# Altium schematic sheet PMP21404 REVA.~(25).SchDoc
size 431 x 279 mm; Date: Not shown in title block; ApprovedBy: Not shown in title block; CheckedBy: Not shown in title block; Author: Not shown in title block; CompanyName: Not shown in title block; Engineer: Not shown in title block; Organization: Not shown in title block; Address1: Not shown in title block; Address2: Not shown in title block; Address3: Not shown in title block; Address4: Not shown in title block; DocumentNumber: 1; Revision: Use project parameter SCH_Rev; SheetNumber: 1; SheetTotal: 1; PageSetup: Record=PageOptions¦CenterHorizontal=True¦CenterVertical=True¦PrintScale=1.00¦XCorrection=1.00¦YCorrection=1.00¦PrintKind=0¦BorderSize=5000000¦LeftOffset=0¦BottomOffset=0¦Orientation=2¦PaperLength=1000¦PaperWidth=1000¦Scale=100¦PaperSource=15¦PrintQuality=600¦MediaType=1¦DitherType=10¦PaperKind=Letter¦PrintScaleMode=1
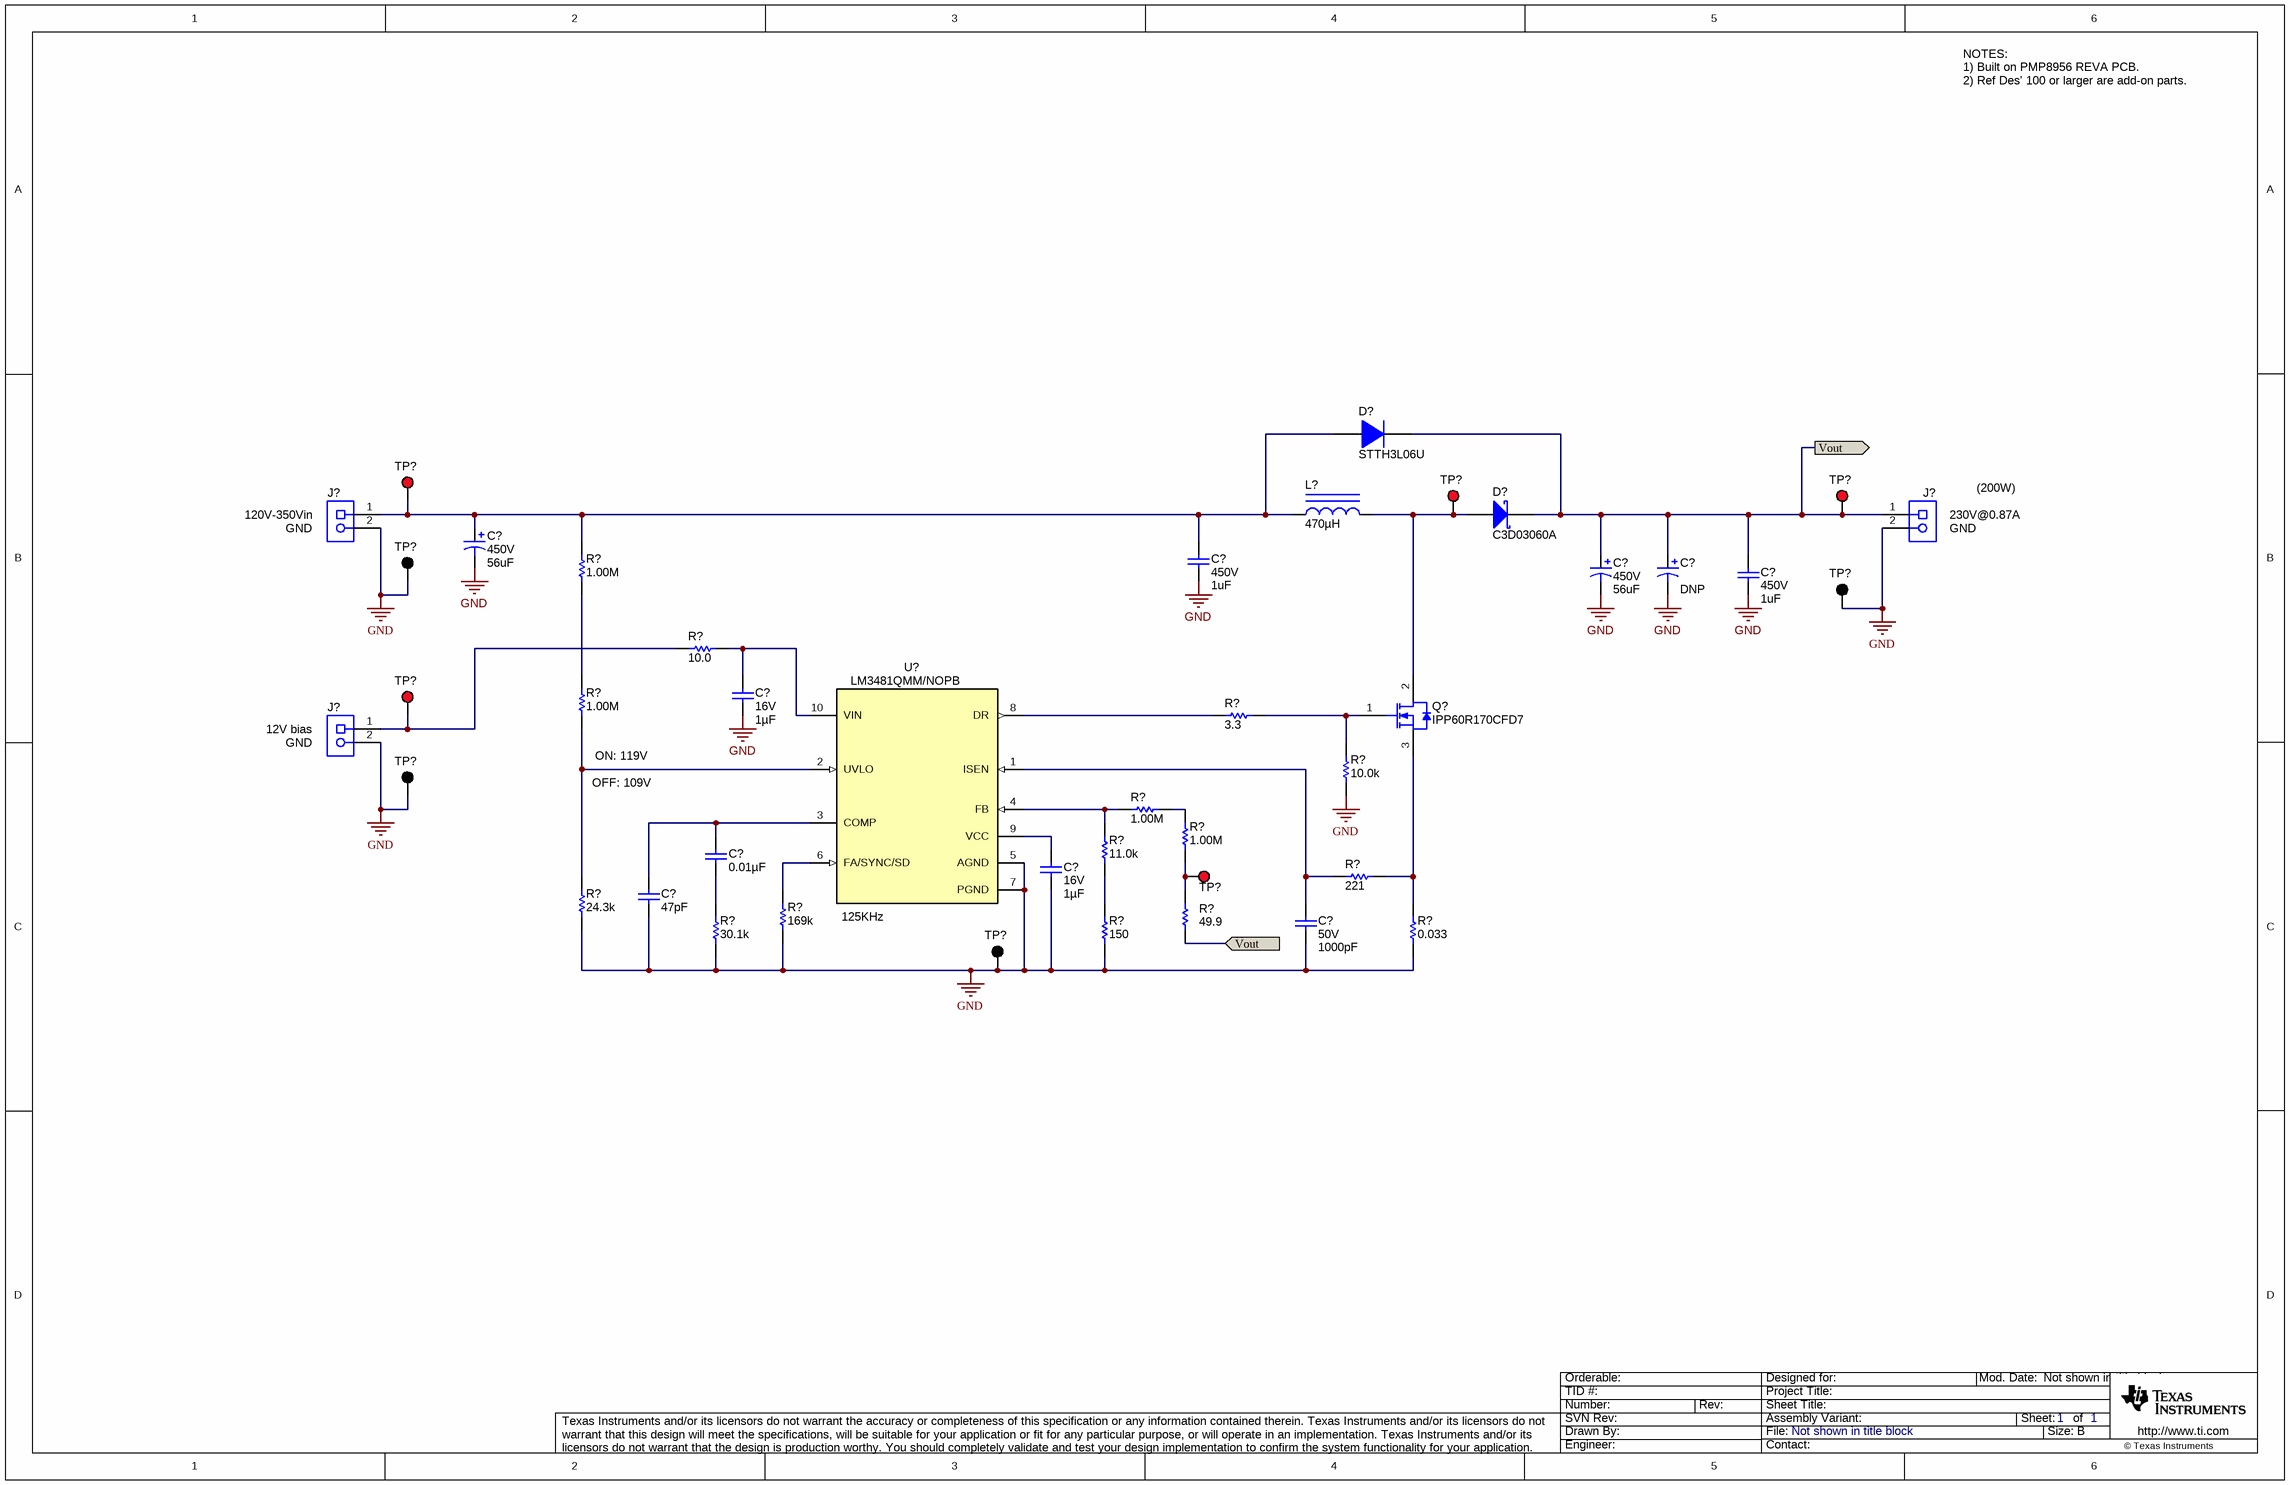
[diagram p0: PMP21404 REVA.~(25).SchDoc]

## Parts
(Parts that share a designator on the sheet are numbered #1, #2 ... from top to bottom, then left to right.)
C?#1  VDC_V: 450V  ValueDisplayed: 56uF  [Nichicon_2000x2500_Snap]  (hidden comment: LLS2W560MELY)
C?#2  VDC_V: 450V  ValueDisplayed: 1uF  [MPK_1800x950]  (hidden comment: 450MPK105J)
C?#3  VDC_V: 450V  ValueDisplayed: 56uF  [Nichicon_2000x2500_Snap]  (hidden comment: LLS2W560MELY)
C?#4  ValueDisplayed: DNP  [Nichicon_2000x2500_Snap]
C?#5  VDC_V: 450V  ValueDisplayed: 1uF  [MPK_1800x950]  (hidden comment: 450MPK105J)
C?#6  VDC_V: 16V  ValueDisplayed: 1µF  [0603]  (hidden comment: CGA3E1X7R1C105K080AC)
C?#7  ValueDisplayed: 0.01µF  [0603]  (hidden comment: C1608X7R1H103K)
C?#8  VDC_V: 16V  ValueDisplayed: 1µF  [0603]  (hidden comment: CGA3E1X7R1C105K080AC)
C?#9  ValueDisplayed: 47pF  [0603]  (hidden comment: C1608C0G1H470J)
C?#10  VDC_V: 50V  ValueDisplayed: 1000pF  [0603]  (hidden comment: GRM188R71H102JA01D)
D?#1  STTH3L06U  [SMB]
D?#2  C3D03060A  [TO-220-2]
J?#1  Receptacle_2x1  [TERM_BLK_ED555-2DS]  (value not drawn)
J?#2  Receptacle_2x1  [TERM_BLK_ED555-2DS]  (value not drawn)
J?#3  Receptacle_2x1  [TERM_BLK_ED555-2DS]  (value not drawn)
L?  ValueDisplayed: 470µH  [Renco_RL1256-3_Pitch_750]  (hidden comment: RL-1256-3-470)
Q?  IPP60R170CFD7  [TO-220AB]
R?#1  ValueDisplayed: 1.00M  [1206]  (hidden comment: CRCW12061M00FKEA)
R?#2  ValueDisplayed: 10.0  [0603]  (hidden comment: CRCW060310R0FKEA)
R?#3  ValueDisplayed: 1.00M  [1206]  (hidden comment: CRCW12061M00FKEA)
R?#4  ValueDisplayed: 3.3  [0603]  (hidden comment: Resistor)
R?#5  ValueDisplayed: 10.0k  [0603]  (hidden comment: CRCW060310K0FKEA)
R?#6  ValueDisplayed: 1.00M  [1206]  (hidden comment: CRCW12061M00FKEA)
R?#7  ValueDisplayed: 1.00M  [1206]  (hidden comment: CRCW12061M00FKEA)
R?#8  ValueDisplayed: 11.0k  [0603]  (hidden comment: CRCW060311K0FKEA)
R?#9  value 221  [0603L]  (hidden comment: Resistor)
R?#10  ValueDisplayed: 24.3k  [0603]  (hidden comment: CRCW060324K3FKEA)
R?#11  ValueDisplayed: 169k  [0603]  (hidden comment: CRCW0603169KFKEA)
R?#12  value 49.9  [0603L]  (hidden comment: Resistor)
R?#13  ValueDisplayed: 30.1k  [0603]  (hidden comment: Resistor)
R?#14  ValueDisplayed: 150  [0603]  (hidden comment: CRCW0603150RFKEA)
R?#15  ValueDisplayed: 0.033  [1206]  (hidden comment: ERJ-8CWFR033V)
TP?#1  5000  [Keystone5000]  (value not drawn)
TP?#2  5000  [Keystone5000]  (value not drawn)
TP?#3  5000  [Keystone5000]  (value not drawn)
TP?#4  5001  [Keystone5001]  (value not drawn)
TP?#5  5001  [Keystone5001]  (value not drawn)
TP?#6  5000  [Keystone5000]  (value not drawn)
TP?#7  5001  [Keystone5001]  (value not drawn)
TP?#8  5000  [Keystone5000]  (value not drawn)
TP?#9  5001  [Keystone5001]  (value not drawn)
U?  LM3481QMM/NOPB  [DGS0010A_N]

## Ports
Vout

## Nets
GND: C?#1.2(-) C?#2.2 C?#3.2(-) C?#4.2(-) C?#5.2 C?#6.2 C?#8.2 C?#9.2 C?#10.2 J?#1.2 J?#2.2 J?#3.2 R?#5.1 R?#10.1 R?#11.1 R?#13.1 R?#14.1 R?#15.1 TP?#4.1 TP?#5.1 TP?#7.1 TP?#9.1 U?.5(AGND) U?.7(PGND)
Vout: C?#3.1(+) C?#4.1(+) C?#5.1 D?#1.1(K) D?#2.1(K) J?#2.1 R?#12.1 TP?#3.1 ; port Vout
NetC?#1_1: C?#1.1(+) C?#2.1 D?#1.2(A) J?#1.1 L?.1 R?#1.2 TP?#1.1
NetC?#6_1: C?#6.1 R?#2.1 U?.10(VIN)
NetC?#7_1: C?#7.1 C?#9.1 U?.3(COMP)
NetC?#7_2: C?#7.2 R?#13.2
NetC?#8_1: C?#8.1 U?.9(VCC)
NetC?#10_1: C?#10.1 R?#9.2 U?.1(ISEN)
NetD?#2_2: D?#2.2(A) L?.2 Q?.2(D) TP?#2.1
NetJ?#3_1: J?#3.1 R?#2.2 TP?#6.1
NetQ?_1: Q?.1(G) R?#4.2 R?#5.2
NetQ?_3: Q?.3(S) R?#9.1 R?#15.2
NetR?#1_1: R?#1.1 R?#3.2
NetR?#3_1: R?#3.1 R?#10.2 U?.2(UVLO)
NetR?#4_1: R?#4.1 U?.8(DR)
NetR?#6_1: R?#6.1 R?#8.2 U?.4(FB)
NetR?#6_2: R?#6.2 R?#7.2
NetR?#7_1: R?#7.1 R?#12.2 TP?#8.1
NetR?#8_1: R?#8.1 R?#14.2
NetR?#11_2: R?#11.2 U?.6(FA/SYNC/SD)

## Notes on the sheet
- NOTES:
  1) Built on PMP8956 REVA PCB.
  2) Ref Des' 100 or larger are add-on parts.
- (200W)
- (near J?#1) 120V-350Vin
- (near J?#1) GND
- (near J?#2) 230V@0.87A
- (near J?#2) GND
- (near J?#3) 12V bias
- (near J?#3) GND
- (near R?#3) ON: 119V
- OFF: 109V
- (near U?) 125KHz

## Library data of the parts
C?#1 C?#3 = CMP-0010119-2: CAP, AL, 56 uF, 450 V, +/- 20%, TH; Manufacturer: Nichicon; TaMin_C: -25°C; Polarized: Y; SizeAreaWB_mm2: 484; Value1: Unknown; U/M: EA; Value: 56uF; TaMax_C: 85°C; SizeZ_mm: 27; SizeX_mm: 20; Cap_Case: 20x25mm; SizeArea_mm2: 400; CompType: Capacitor; AEC Qualified: N; Cap_F: 56µF; IRMS_A: 6.1dA; AEC Category: Q200
C?#2 C?#5 = CMP-0012307-3: CAP, Film, 1 uF, 450 V, +/- 5%, TH; Manufacturer: Rubycon; TaMin_C: -40°C; Polarized: N; Value1: Unknown; Value: 1uF; TaMax_C: 105°C; Cap_Case: 18x9.5mm; Cap_F: 1µF; AEC Category: Q200
C?#4 = CMP-0010119-2: CAP, AL, DNP; TaMin_C: -25°C; Polarized: Y; SizeAreaWB_mm2: 484; Value1: Unknown; U/M: EA; TaMax_C: 85°C; Tolerance_%: 20%; SizeZ_mm: 27; SizeX_mm: 20; Cap_Case: 20x25mm; SizeArea_mm2: 400; CompType: Capacitor; AEC Qualified: N; AEC Category: Q200
C?#6 C?#8 = CMP-0079607-1: CAP, CERM, 1 µF, 16 V,+/- 10%, X7R, AEC-Q200 Grade 1, 0603; Manufacturer: TDK; TaMin_C: -55°C; Polarized: N; SizeAreaWB_mm2: 4.68; U/M: EA; Value: 1uF; TaMax_C: 125°C; SizeZ_mm: 1; SizeX_mm: 1.6; SizeY_mm: 0.8; SizeArea_mm2: 1.28; AEC Qualified: Y; AEC Category: Q200
C?#7 = C1608X7R1H103K: CAP, CERM, 0.01uF, 50V, +/-10%, X7R, 0603; Manufacturer: TDK; Polarized: N; CompType: Capacitor; U/M: EA; Cap_F: 0.00000001; Tolerance_%: 10; ESR_Ohm: 0.0539; Value1: 0.0539 ohm; VDC_V: 50; TaMin_C: -55; TaMax_C: 125
C?#9 = C1608C0G1H470J: CAP, CERM, 47pF, 50V, +/-5%, C0G/NP0, 0603; Manufacturer: TDK; Polarized: N; CompType: Capacitor; U/M: EA; Cap_F: 0.000000000047; Tolerance_%: 5; ESR_Ohm: 0.22; Value1: 0.22 ohm; VDC_V: 50; TaMin_C: -55; TaMax_C: 125
C?#10 = CMP-0007431-4: CAP, CERM, 1000 pF, 50 V, +/- 5%, X7R, 0603; Manufacturer: MuRata; TaMin_C: -55°C; Polarized: N; SizeAreaWB_mm2: 4.68; Value1: Unknown; U/M: EA; Value: 1000pF; TaMax_C: 125°C; SizeZ_mm: 1; SizeX_mm: 1.6; SizeY_mm: 0.8; SizeArea_mm2: 1.28; Cap_F: 1nF; AEC Category: Q200
D?#1 = CMP-0077014-1: Diode, Ultrafast, 600 V, 3 A, SMB; Manufacturer: STMicroelectronics; SizeAreaWB_mm2: 44.156; Vr_V: 600V; SizeArea_mm2: 21.336; TJmax_C: 175°C; AEC Category: Q101; Value: 600V; SizeZ_mm: 2.6; Green_REACh: Incomplete; Io_A: 3A; Vf_V: 1.3V; SizeY_mm: 3.81; Green_Lifecycle: Not Set; U/M: EA; SizeX_mm: 5.6
D?#2 = CMP-0079543-1: Diode, Schottky, 600 V, 11 A, AEC-Q101, TH; Manufacturer: Cree; SizeAreaWB_mm2: 77.630025; Vr_V: 600V; SizeArea_mm2: 44.650025; AEC Qualified: Y; TJmax_C: 175°C; AEC Category: Q101; Value: 600V; SizeZ_mm: 20; Green_REACh: Incomplete; Io_A: 11A; SizeY_mm: 4.445; Green_Lifecycle: Active; SizeX_mm: 10.045; RJC_CperW: 3.2
J?#1-J?#3 = CMP-0074913-1: Terminal Block, 3.5mm Pitch, 2x1, TH; PartNumber: ED555/2DS; Manufacturer: On-Shore Technology; Cert_CULUS: Y; CNHeader: False; ContactFinish: Brass; CT: True; Current_A: 6A; Gender: Female; Green_Lifecycle: Active; Green_REACh: Passed; Pitch_mm: 3.5; Row_Count: 1; Shrouded: N; Voltage_V: 150V
L? = CMP-0077831-1: Inductor, 470 µH, 4 A, 0.187 ohm, TH; Manufacturer: Renco Electronics; SizeAreaWB_mm2: 896.4036; Irms: 4A @ 40C rise; SizeArea_mm2: 780.6436; AEC Qualified: N; AEC Category: Q200; Value: 470uH; SizeZ_mm: 21.59; Imax_A: 4A; SizeY_mm: 27.94; Isat: 6A @ 5% inductance drop; DCR_ohm: 1.87d
Q? = CMP-0001174-3: MOSFET, N-CH, 600 V, 51 A, TO-220AB; Alternate Manufacturer: None; Manufacturer: Infineon Technologies; SizeZ_mm: 19.4; ChType: N; Value2: 28 nC; VdsMax_V: 600V; SizeX_mm: 10.2; SizeY_mm: 4.5; Vgs_V: 20V; Value: 600V; SizeArea_mm2: 45.9; AEC Category: Q101; IdsMax_A: 51A; SizeAreaWB_mm2: 79.3; U/M: EA; QgTyp_nC: 28
R?#1 R?#3 R?#6 R?#7 = CMP-0016716-3: RES, 1.00 M, 1%, 0.25 W, AEC-Q200 Grade 0, 1206; Manufacturer: Vishay-Dale; Power_W: 250mW; TempCo: 100 ppm/C; Value_Code: 1M00; Value: 1.00Meg; EIA_Code: E96; Res_ohm: 1M; SizeX_mm: 3.2; SizeY_mm: 1.6; SizeZ_mm: 1.35; Value2: 0.25W; SizeArea_mm2: 5.12; AEC Qualified: Y; VDC_V: 200V; AEC Category: Q200; AEC Grade: 0
R?#2 = CMP-0022003-4: RES, 10.0, 1%, 0.1 W, AEC-Q200 Grade 0, 0603; Manufacturer: Vishay-Dale; Power_W: 100mW; TempCo: 100 ppm/C; Value_Code: 10R0; Value: 10.0; EIA_Code: E96; Res_ohm: 10; SizeX_mm: 1.6; SizeY_mm: 0.8; SizeZ_mm: 1; Value2: 0.1W; SizeArea_mm2: 1.28; AEC Qualified: Y; VDC_V: 75V; AEC Category: Q200; AEC Grade: 0
R?#4 = CMP-0025805-4: RES, 3.3, 5%, 0.1 W, AEC-Q200 Grade 0, 0603; PartNumber: CRCW06033R30JNEA; Manufacturer: Vishay-Dale; Value: 3.3; Value_Code: 3R30; Power_W: 100mW; Value2: 0.1W; VDC_V: 75V; TempCo: 200 ppm/C; EIA_Code: E24; AEC Category: Q200; AEC Qualified: Y; AEC Grade: 0; SizeArea_mm2: 1.28; SizeX_mm: 1.6; SizeY_mm: 0.8; SizeZ_mm: 1
R?#5 = CMP-0021998-4: RES, 10.0 k, 1%, 0.1 W, AEC-Q200 Grade 0, 0603; Manufacturer: Vishay-Dale; Power_W: 100mW; TempCo: 100 ppm/C; Value_Code: 10k0; Value: 10.0k; EIA_Code: E96; Res_ohm: 10k; SizeX_mm: 1.6; SizeY_mm: 0.8; SizeZ_mm: 1; Value2: 0.1W; SizeArea_mm2: 1.28; AEC Qualified: Y; VDC_V: 75V; AEC Category: Q200; AEC Grade: 0
R?#8 = CMP-0022016-4: RES, 11.0 k, 1%, 0.1 W, AEC-Q200 Grade 0, 0603; Manufacturer: Vishay-Dale; Power_W: 100mW; TempCo: 100 ppm/C; Value_Code: 11k0; Value: 11.0k; EIA_Code: E96; Res_ohm: 11k; SizeX_mm: 1.6; SizeY_mm: 0.8; SizeZ_mm: 1; Value2: 0.1W; SizeArea_mm2: 1.28; AEC Qualified: Y; VDC_V: 75V; AEC Category: Q200; AEC Grade: 0
R?#9 = CMP-0022217-5: RES, 221, 1%, 0.1 W, AEC-Q200 Grade 0, 0603; PartNumber: CRCW0603221RFKEA; Manufacturer: Vishay-Dale; Value_Code: 221R; Power_W: 100mW; Value2: 0.1W; VDC_V: 75V; TempCo: 100 ppm/C; EIA_Code: E96; AEC Category: Q200; AEC Grade: 0; AEC Qualified: Y; SizeArea_mm2: 1.28; SizeX_mm: 1.6; SizeY_mm: 0.8; SizeZ_mm: 1
R?#10 = CMP-0022236-4: RES, 24.3 k, 1%, 0.1 W, AEC-Q200 Grade 0, 0603; Manufacturer: Vishay-Dale; Power_W: 100mW; TempCo: 100 ppm/C; Value_Code: 24k3; Value: 24.3k; EIA_Code: E96; SizeX_mm: 1.6; SizeY_mm: 0.8; SizeZ_mm: 1; Value2: 0.1W; SizeArea_mm2: 1.28; AEC Qualified: Y; VDC_V: 75V; AEC Category: Q200; AEC Grade: 0
R?#11 = CMP-0022077-4: RES, 169 k, 1%, 0.1 W, AEC-Q200 Grade 0, 0603; Manufacturer: Vishay-Dale; Power_W: 100mW; TempCo: 100 ppm/C; Value: 169k; EIA_Code: E96; SizeX_mm: 1.6; SizeY_mm: 0.8; SizeZ_mm: 1; Value2: 0.1W; SizeArea_mm2: 1.28; AEC Qualified: Y; VDC_V: 75V; AEC Category: Q200; AEC Grade: 0
R?#12 = CMP-0022448-4: RES, 49.9, 1%, 0.1 W, AEC-Q200 Grade 0, 0603; PartNumber: CRCW060349R9FKEA; Manufacturer: Vishay-Dale; Value_Code: 49R9; Power_W: 100mW; Value2: 0.1W; VDC_V: 75V; TempCo: 100 ppm/C; EIA_Code: E96; AEC Category: Q200; AEC Grade: 0; AEC Qualified: Y; SizeArea_mm2: 1.28; SizeX_mm: 1.6; SizeY_mm: 0.8; SizeZ_mm: 1
R?#13 = CMP-0022324-4: RES, 30.1 k, 1%, 0.1 W, AEC-Q200 Grade 0, 0603; PartNumber: CRCW060330K1FKEA; Manufacturer: Vishay-Dale; Value: 30.1k; Value_Code: 30k1; Power_W: 100mW; Value2: 0.1W; VDC_V: 75V; TempCo: 100 ppm/C; EIA_Code: E96; AEC Category: Q200; AEC Qualified: Y; AEC Grade: 0; SizeArea_mm2: 1.28; SizeX_mm: 1.6; SizeY_mm: 0.8; SizeZ_mm: 1
R?#14 = CMP-0022061-5: RES, 150, 1%, 0.1 W, AEC-Q200 Grade 0, 0603; Manufacturer: Vishay-Dale; Power_W: 100mW; TempCo: 100 ppm/C; Value_Code: 150R; Value: 150; EIA_Code: E96; SizeX_mm: 1.6; SizeY_mm: 0.8; SizeZ_mm: 1; Value2: 0.1W; SizeArea_mm2: 1.28; AEC Qualified: Y; VDC_V: 75V; AEC Category: Q200; AEC Grade: 0
R?#15 = CMP-0017280-2: RES, 0.033, 1%, 1 W, AEC-Q200 Grade 0, 1206; Manufacturer: Panasonic; Power_W: 1W; TempCo: 50 ppm/C; Value_Code: R033; U/M: EA; Value: 0.033; EIA_Code: E96; SizeX_mm: 3.2; SizeY_mm: 1.6; SizeZ_mm: 1.35; SizeArea_mm2: 5.12; AEC Qualified: Y; AEC Grade: 0; AEC Category: Q200
TP?#1-TP?#3 TP?#6 TP?#8 = CMP-0055137-1: Test Point, Miniature, Red, TH; Manufacturer: Keystone; CNHeader: FALSE; ContactFinish: Silver; CT: TRUE; Green_Lifecycle: Active; Green_REACh: Passed
TP?#4 TP?#5 TP?#7 TP?#9 = CMP-0055138-1: Test Point, Miniature, Black, TH; Manufacturer: Keystone; CNHeader: FALSE; ContactFinish: Silver; CT: TRUE; Green_Lifecycle: Active; Green_REACh: Passed
U? = CMP-0071928-2: High Efficiency Low-Side N-Channel Controller for Switching Regulators, AEC-Q100 Grade 1, 10-pin Mini SOIC, 1000 Reel; Manufacturer: Texas Instruments; Alternate PartNumber: LM3481QMMX/NOPB; CompType: IC; AEC Category: Q200; AEC Qualified: Y; SizeAreaWB_mm2: 23.6; SizeArea_mm2: 14.7; SizeX_mm: 4.9; SizeY_mm: 3; SizeZ_mm: 1.1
